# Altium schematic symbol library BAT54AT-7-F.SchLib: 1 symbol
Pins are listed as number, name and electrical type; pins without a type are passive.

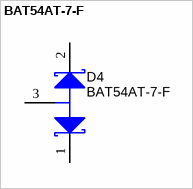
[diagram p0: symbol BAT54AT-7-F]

## BAT54AT-7-F
designator D4
Diode, Schottky, 30 V, 0.2 A, SOT-523; Manufacturer: Diodes Inc.; U/M: EA; Vf_V: 0.7; Value: 30V; Value1: 0.2A; Value2: 0.7V; Io_A: 0.2; Vr_V: 30; TJmax_C: 125
signal-integrity model Diode
footprint SOT-523
pins: 1 A1, 2 A2, 3 K
1 alternate drawing of the same symbol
